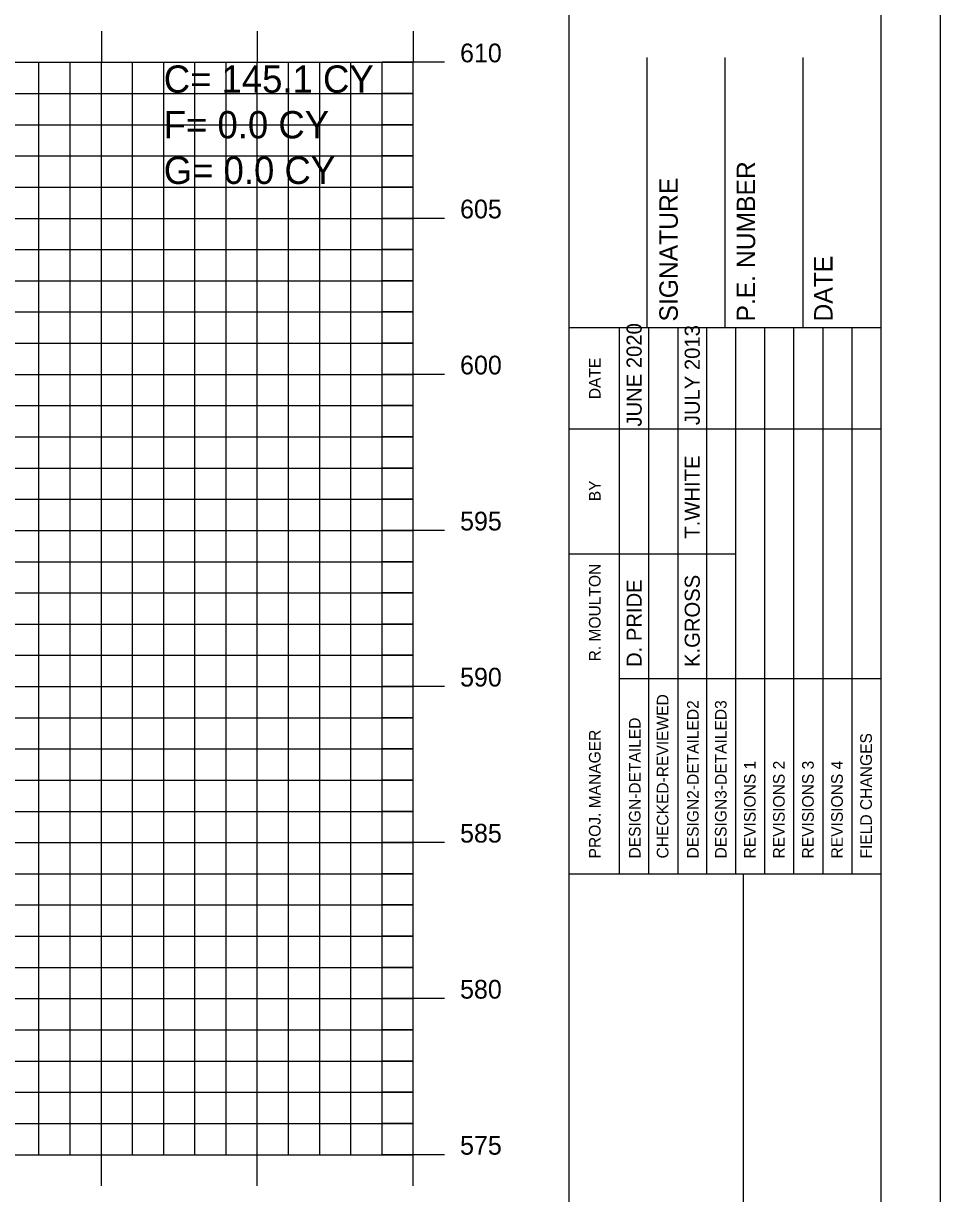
# Model space of a CAD drawing. Extents: x 1076304 to 1076474, y 779716 to 779826.
# Drawn here: x 1076444.29 to 1076473.7, y 779753.46 to 779790.95 of the extents above; entities that cross this region are included whole.
import ezdxf

# ---------------------------------------------------------------- set-up
doc = ezdxf.new("R2010")
doc.units = 0
for name, color, linetype in [('BORDER', 7, 'Continuous'), ('H_V ANNOTATION', 7, 'Continuous'), ('MAJOR', 7, 'Continuous'), ('MINOR', 7, 'Continuous'), ('PLOT BOUNDARY', 7, 'Continuous')]:
    doc.layers.add(name, color=color, linetype=linetype)

msp = doc.modelspace()

# ---------------------------------------------------------------- linework, layer by layer
at = {"layer": 'BORDER'}
for p, q in [((1076461.794, 779718.706), (1076461.794, 779823.706)), ((1076464.294, 779781.209), (1076464.294, 779789.856)), ((1076466.794, 779781.209), (1076466.794, 779789.856)), ((1076469.294, 779781.209), (1076469.294, 779789.856)), ((1076461.794, 779781.209), (1076471.794, 779781.209)), ((1076461.794, 779763.709), (1076471.794, 779763.709)), ((1076467.385, 779728.709), (1076467.385, 779763.709))]:
    msp.add_line(p, q, dxfattribs=at)
msp.add_lwpolyline([(1076311.794, 779718.706), (1076471.794, 779718.706), (1076471.794, 779823.706), (1076311.794, 779823.706)], close=True, dxfattribs=at)
for points in [[(1076463.409, 779777.959), (1076463.409, 779781.209)], [(1076464.342, 779763.712), (1076464.342, 779781.209)], [(1076465.274, 779781.209), (1076465.274, 779763.712)], [(1076466.205, 779763.712), (1076466.205, 779781.209)], [(1076467.137, 779763.712), (1076467.137, 779781.209)], [(1076468.069, 779763.712), (1076468.069, 779781.209)], [(1076469, 779763.712), (1076469, 779781.209)], [(1076469.932, 779763.712), (1076469.932, 779781.209)], [(1076470.864, 779763.712), (1076470.864, 779781.209)], [(1076463.41, 779763.712), (1076463.41, 779780.503)], [(1076461.794, 779777.959), (1076471.794, 779777.959)], [(1076461.794, 779773.959), (1076463.41, 779773.959)], [(1076463.409, 779773.959), (1076467.136, 779773.959)], [(1076463.409, 779769.959), (1076471.794, 779769.959)]]:
    msp.add_lwpolyline(points, dxfattribs=at)
at = {"layer": 'MAJOR'}
for p, q in [((1076446.794, 779790.708), (1076446.794, 779789.706)), ((1076451.794, 779790.708), (1076451.794, 779789.706)), ((1076456.794, 779790.708), (1076456.794, 779789.706)), ((1076316.794, 779789.706), (1076456.794, 779789.706)), ((1076316.794, 779789.706), (1076456.794, 779789.706)), ((1076446.794, 779754.706), (1076446.794, 779789.706)), ((1076451.794, 779754.706), (1076451.794, 779789.706)), ((1076457.796, 779789.706), (1076455.792, 779789.706)), ((1076456.794, 779754.706), (1076456.794, 779789.706)), ((1076456.794, 779754.706), (1076456.794, 779789.706)), ((1076316.794, 779784.706), (1076456.794, 779784.706)), ((1076457.796, 779784.706), (1076455.792, 779784.706)), ((1076316.794, 779779.706), (1076456.794, 779779.706)), ((1076457.796, 779779.706), (1076455.792, 779779.706)), ((1076316.794, 779774.706), (1076456.794, 779774.706)), ((1076457.796, 779774.706), (1076455.792, 779774.706)), ((1076316.794, 779769.706), (1076456.794, 779769.706)), ((1076457.796, 779769.706), (1076455.792, 779769.706)), ((1076316.794, 779764.706), (1076456.794, 779764.706)), ((1076457.796, 779764.706), (1076455.792, 779764.706)), ((1076316.794, 779759.706), (1076456.794, 779759.706)), ((1076457.796, 779759.706), (1076455.792, 779759.706)), ((1076316.794, 779754.706), (1076456.794, 779754.706)), ((1076316.794, 779754.706), (1076456.794, 779754.706)), ((1076446.794, 779753.704), (1076446.794, 779754.706)), ((1076451.794, 779753.704), (1076451.794, 779754.706)), ((1076457.796, 779754.706), (1076455.792, 779754.706)), ((1076456.794, 779753.704), (1076456.794, 779754.706))]:
    msp.add_line(p, q, dxfattribs=at)
at = {"layer": 'MINOR'}
for p, q in [((1076444.794, 779754.706), (1076444.794, 779789.706)), ((1076445.794, 779754.706), (1076445.794, 779789.706)), ((1076447.794, 779754.706), (1076447.794, 779789.706)), ((1076448.794, 779754.706), (1076448.794, 779789.706)), ((1076449.794, 779754.706), (1076449.794, 779789.706)), ((1076450.794, 779754.706), (1076450.794, 779789.706)), ((1076452.794, 779754.706), (1076452.794, 779789.706)), ((1076453.794, 779754.706), (1076453.794, 779789.706)), ((1076454.794, 779754.706), (1076454.794, 779789.706)), ((1076455.794, 779754.706), (1076455.794, 779789.706)), ((1076316.794, 779788.706), (1076456.794, 779788.706)), ((1076456.794, 779788.706), (1076455.792, 779788.706)), ((1076316.794, 779787.706), (1076456.794, 779787.706)), ((1076456.794, 779787.706), (1076455.792, 779787.706)), ((1076316.794, 779786.706), (1076456.794, 779786.706)), ((1076456.794, 779786.706), (1076455.792, 779786.706)), ((1076316.794, 779785.706), (1076456.794, 779785.706)), ((1076456.794, 779785.706), (1076455.792, 779785.706)), ((1076316.794, 779783.706), (1076456.794, 779783.706)), ((1076456.794, 779783.706), (1076455.792, 779783.706)), ((1076316.794, 779782.706), (1076456.794, 779782.706)), ((1076456.794, 779782.706), (1076455.792, 779782.706)), ((1076316.794, 779781.706), (1076456.794, 779781.706)), ((1076456.794, 779781.706), (1076455.792, 779781.706)), ((1076316.794, 779780.706), (1076456.794, 779780.706)), ((1076456.794, 779780.706), (1076455.792, 779780.706)), ((1076316.794, 779778.706), (1076456.794, 779778.706)), ((1076456.794, 779778.706), (1076455.792, 779778.706)), ((1076316.794, 779777.706), (1076456.794, 779777.706)), ((1076456.794, 779777.706), (1076455.792, 779777.706)), ((1076316.794, 779776.706), (1076456.794, 779776.706)), ((1076456.794, 779776.706), (1076455.792, 779776.706)), ((1076316.794, 779775.706), (1076456.794, 779775.706)), ((1076456.794, 779775.706), (1076455.792, 779775.706)), ((1076316.794, 779773.706), (1076456.794, 779773.706)), ((1076456.794, 779773.706), (1076455.792, 779773.706)), ((1076316.794, 779772.706), (1076456.794, 779772.706)), ((1076456.794, 779772.706), (1076455.792, 779772.706)), ((1076316.794, 779771.706), (1076456.794, 779771.706)), ((1076456.794, 779771.706), (1076455.792, 779771.706)), ((1076316.794, 779770.706), (1076456.794, 779770.706)), ((1076456.794, 779770.706), (1076455.792, 779770.706)), ((1076316.794, 779768.706), (1076456.794, 779768.706)), ((1076456.794, 779768.706), (1076455.792, 779768.706)), ((1076316.794, 779767.706), (1076456.794, 779767.706)), ((1076456.794, 779767.706), (1076455.792, 779767.706)), ((1076316.794, 779766.706), (1076456.794, 779766.706)), ((1076456.794, 779766.706), (1076455.792, 779766.706)), ((1076316.794, 779765.706), (1076456.794, 779765.706)), ((1076456.794, 779765.706), (1076455.792, 779765.706)), ((1076316.794, 779763.706), (1076456.794, 779763.706)), ((1076456.794, 779763.706), (1076455.792, 779763.706)), ((1076316.794, 779762.706), (1076456.794, 779762.706)), ((1076456.794, 779762.706), (1076455.792, 779762.706)), ((1076316.794, 779761.706), (1076456.794, 779761.706)), ((1076456.794, 779761.706), (1076455.792, 779761.706)), ((1076316.794, 779760.706), (1076456.794, 779760.706)), ((1076456.794, 779760.706), (1076455.792, 779760.706)), ((1076316.794, 779758.706), (1076456.794, 779758.706)), ((1076456.794, 779758.706), (1076455.792, 779758.706)), ((1076316.794, 779757.706), (1076456.794, 779757.706)), ((1076456.794, 779757.706), (1076455.792, 779757.706)), ((1076316.794, 779756.706), (1076456.794, 779756.706)), ((1076456.794, 779756.706), (1076455.792, 779756.706)), ((1076316.794, 779755.706), (1076456.794, 779755.706)), ((1076456.794, 779755.706), (1076455.792, 779755.706))]:
    msp.add_line(p, q, dxfattribs=at)
at = {"layer": 'PLOT BOUNDARY'}
msp.add_lwpolyline([(1076303.701, 779715.646), (1076473.701, 779715.646), (1076473.701, 779825.646), (1076303.701, 779825.646)], close=True, dxfattribs=at)

# ---------------------------------------------------------------- texts
at = {"layer": 'BORDER'}
for s, height, p in [('P.E. NUMBER', 0.59055, (1076467.755, 779781.401)), ('SIGNATURE', 0.5906, (1076465.275, 779781.401)), ('DATE', 0.5906, (1076470.236, 779781.401)), ('JUNE 2020', 0.4845, (1076464.117, 779778.034)), ('JULY 2013', 0.4845, (1076465.981, 779778.08)), ('DATE', 0.3714, (1076462.799, 779778.914)), ('T.WHITE', 0.4845, (1076465.981, 779774.444)), ('BY', 0.3714, (1076462.799, 779775.644)), ('R. MOULTON', 0.3727, (1076462.799, 779770.511)), ('D. PRIDE', 0.4845, (1076464.117, 779770.332)), ('K.GROSS', 0.4845, (1076465.981, 779770.332)), ('CHECKED-REVIEWED', 0.37275, (1076464.975, 779764.197)), ('DESIGN2-DETAILED2', 0.37275, (1076465.944, 779764.197)), ('DESIGN3-DETAILED3', 0.37275, (1076466.839, 779764.197)), ('DESIGN-DETAILED', 0.37275, (1076464.081, 779764.197)), ('PROJ. MANAGER', 0.37275, (1076462.799, 779764.197)), ('FIELD CHANGES', 0.37275, (1076471.497, 779764.197)), ('REVISIONS 1', 0.37275, (1076467.771, 779764.197)), ('REVISIONS 2', 0.37275, (1076468.702, 779764.197)), ('REVISIONS 3', 0.37275, (1076469.634, 779764.197)), ('REVISIONS 4', 0.37275, (1076470.566, 779764.197))]:
    msp.add_text(s, height=height, rotation=90, dxfattribs=at).set_placement(p)
at = {"layer": 'H_V ANNOTATION'}
for s, height, p in [('610', 0.6, (1076458.294, 779789.706)), ('C= 145.1 CY', 0.87498, (1076448.794, 779788.731)), ('F= 0.0 CY', 0.875, (1076448.794, 779787.269)), ('G= 0.0 CY', 0.875, (1076448.794, 779785.808)), ('605', 0.6, (1076458.294, 779784.706)), ('600', 0.6, (1076458.294, 779779.706)), ('595', 0.6, (1076458.294, 779774.706)), ('590', 0.6, (1076458.294, 779769.706)), ('585', 0.6, (1076458.294, 779764.706)), ('580', 0.6, (1076458.294, 779759.706)), ('575', 0.6, (1076458.294, 779754.706))]:
    msp.add_text(s, height=height, dxfattribs=at).set_placement(p)

doc.saveas('drawing.dxf')
